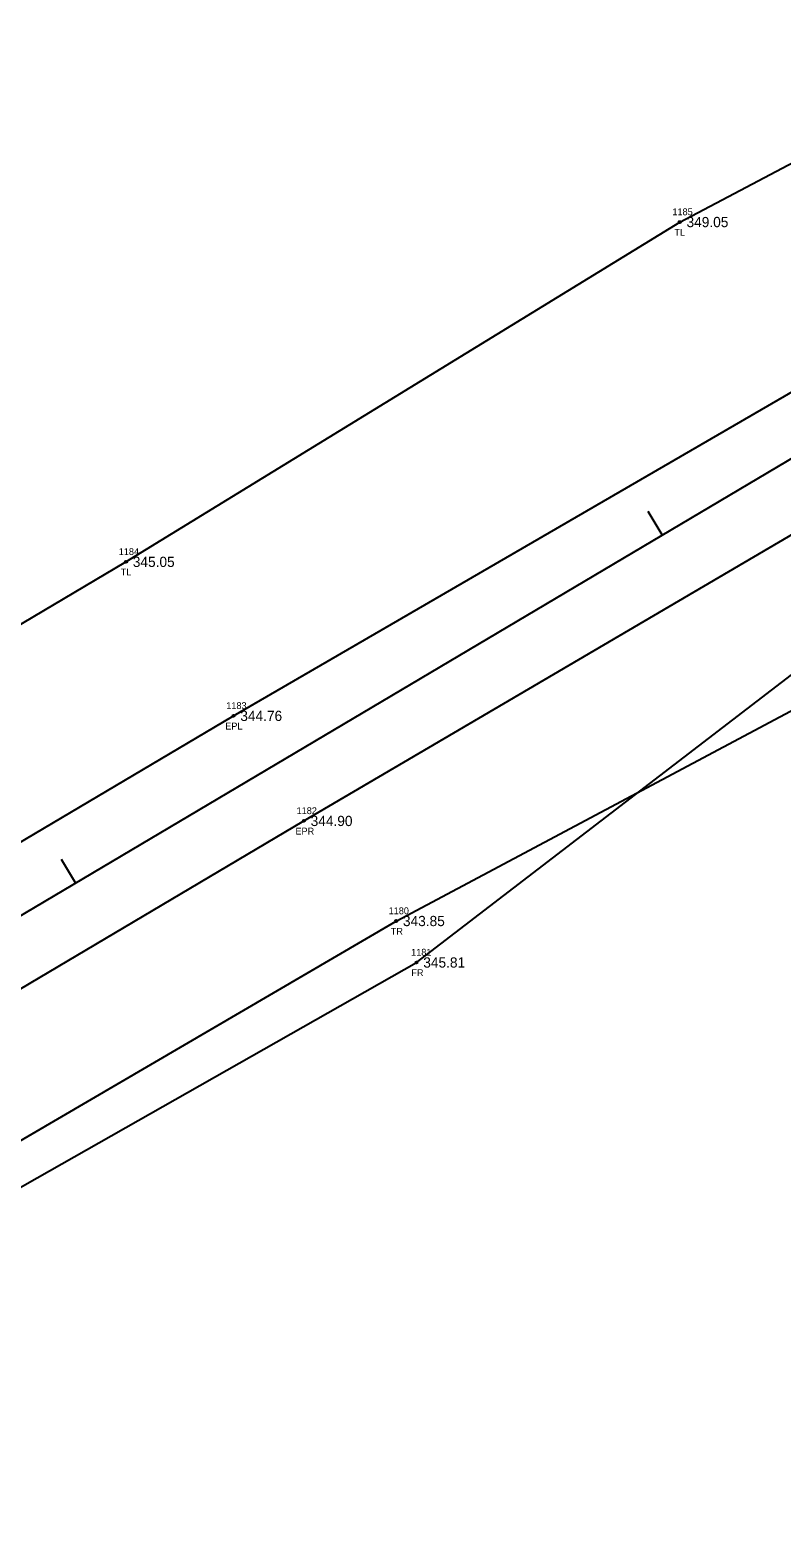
# Model space of a CAD drawing. Extents: x 2231119 to 2232595, y 1035731 to 1037094.
# Drawn here: x 2232076.9 to 2232187.1, y 1036650 to 1036871.1 of the extents above; entities that cross this region are included whole.
import ezdxf

# ---------------------------------------------------------------- set-up
doc = ezdxf.new("R2010")
doc.units = 0
for name, color, linetype in [('RD_EX_Fence_Other', 7, 'Continuous'), ('RD_EX_Fence_Other_txCode', 7, 'Continuous'), ('RD_EX_Road', 7, 'Continuous'), ('RD_EX_Road_txCode', 7, 'Continuous'), ('RD_EX_TX_Fence_Other_ELEV', 7, 'Continuous'), ('RD_EX_TX_Road_ELEV', 7, 'Continuous'), ('RD_EX_TX_VEG_ELEV', 7, 'Continuous'), ('RD_EX_VEG', 7, 'Continuous'), ('RD_EX_VEG_txCode', 7, 'Continuous'), ('RD_HC_Cl', 7, 'Continuous'), ('RD_HC_Data_Tic', 7, 'Continuous'), ('RD_SMD_Locator', 7, 'Continuous')]:
    doc.layers.add(name, color=color, linetype=linetype)

msp = doc.modelspace()

# ---------------------------------------------------------------- linework, layer by layer
at = {"layer": 'RD_EX_Fence_Other'}
msp.add_lwpolyline([(2231742.82, 1036485.51), (2231730.99, 1036494.96), (2231789.88, 1036531.02), (2231876.81, 1036583.89), (2231964.37, 1036635.23), (2232046.18, 1036684.79), (2232133.57, 1036734.4), (2232210.6, 1036793.49), (2232301.78, 1036835.03)], dxfattribs=at)
at = {"layer": 'RD_EX_Road'}
for points in [[(2231606.1, 1036462.92), (2231601.27, 1036470.82), (2231681.58, 1036519.84), (2231764.99, 1036568.78), (2231851.5, 1036619.95), (2231935.62, 1036669.65), (2232021.78, 1036720.22), (2232106.75, 1036770.57), (2232190.54, 1036819.2), (2232275.92, 1036870.27)], [(2231606.1, 1036462.92), (2231610.57, 1036455.36), (2231692.09, 1036503.24), (2231706.07, 1036512.59), (2231777.1, 1036553.27), (2231861.39, 1036604.65), (2231946.39, 1036654.77), (2232031.07, 1036704.2), (2232117.06, 1036755.16), (2232199.91, 1036803.8), (2232286.7, 1036855.36)]]:
    msp.add_lwpolyline(points, dxfattribs=at)
at = {"layer": 'RD_EX_VEG'}
for points in [[(2231598.25, 1036478.35), (2231674.54, 1036527.95), (2231759.25, 1036584.63), (2231839.99, 1036637.88), (2231924.53, 1036692.24), (2232004.98, 1036742.14), (2232090.99, 1036793.16), (2232172.16, 1036843), (2232262.27, 1036890.61)], [(2231753.59, 1036474.98), (2231730.55, 1036496.34), (2231788.45, 1036533.87), (2231871.45, 1036588.79), (2231958.94, 1036639.51), (2232040.64, 1036687.92), (2232130.59, 1036740.48), (2232213.07, 1036784.39), (2232299.54, 1036835.55)]]:
    msp.add_lwpolyline(points, dxfattribs=at)
at = {"layer": 'RD_HC_Cl'}
msp.add_line((2231548.98, 1036428.87), (2232281.06, 1036863.23), dxfattribs=at)
at = {"layer": 'RD_HC_Data_Tic'}
for p, q in [((2232169.6, 1036797.1), (2232167.56, 1036800.54)), ((2232083.6, 1036746.08), (2232081.56, 1036749.52))]:
    msp.add_line(p, q, dxfattribs=at)
at = {"layer": 'RD_SMD_Locator'}
for centre in [(2232172.16, 1036843), (2232090.99, 1036793.16), (2232106.75, 1036770.57), (2232117.06, 1036755.16), (2232130.59, 1036740.48), (2232133.57, 1036734.4)]:
    msp.add_circle(centre, 0.15, dxfattribs=at)

# ---------------------------------------------------------------- texts
at = {"layer": 'RD_EX_Fence_Other_txCode'}
for s, p in [('1181', (2232132.79, 1036735.4)), ('FR', (2232132.82, 1036732.4))]:
    msp.add_text(s, height=1, dxfattribs=at).set_placement(p)
at = {"layer": 'RD_EX_Road_txCode'}
for s, p in [('1183', (2232105.69, 1036771.57)), ('EPL', (2232105.54, 1036768.57)), ('1182', (2232116, 1036756.16)), ('EPR', (2232115.83, 1036753.16))]:
    msp.add_text(s, height=1, dxfattribs=at).set_placement(p)
at = {"layer": 'RD_EX_TX_Fence_Other_ELEV'}
msp.add_text('345.81', height=1.5, dxfattribs=at).set_placement((2232134.57, 1036733.65))
at = {"layer": 'RD_EX_TX_Road_ELEV'}
for s, p in [('344.76', (2232107.75, 1036769.82)), ('344.90', (2232118.06, 1036754.41))]:
    msp.add_text(s, height=1.5, dxfattribs=at).set_placement(p)
at = {"layer": 'RD_EX_TX_VEG_ELEV'}
for s, p in [('349.05', (2232173.16, 1036842.25)), ('345.05', (2232091.99, 1036792.41)), ('343.85', (2232131.59, 1036739.73))]:
    msp.add_text(s, height=1.5, dxfattribs=at).set_placement(p)
at = {"layer": 'RD_EX_VEG_txCode'}
for s, p in [('1185', (2232171.09, 1036844)), ('TL', (2232171.38, 1036841)), ('1184', (2232089.93, 1036794.16)), ('TL', (2232090.22, 1036791.16)), ('1180', (2232129.49, 1036741.48)), ('TR', (2232129.8, 1036738.48))]:
    msp.add_text(s, height=1, dxfattribs=at).set_placement(p)

doc.saveas('drawing.dxf')
